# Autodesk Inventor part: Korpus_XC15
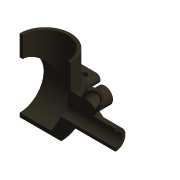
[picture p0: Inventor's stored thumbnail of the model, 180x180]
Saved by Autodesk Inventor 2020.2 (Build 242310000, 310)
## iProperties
Created: 2000-05
Part Number: Korpus_XC15
Document SubType Name: Modeling
Designer: F.Stasiak
Stock Number: Korpus_XC15
Density: 7.15 g/cm^3
Material: Żelazo, odlew
Appearance: Brąz armatni (nowy/polerowany)
Mass: 7300.3 g
Surface Area: 1792.14 cm^2
Volume: 1021.02 cm^3
Catalog Web Link: www.expertbooks.pl
Manager: www.cadconsulting.pl
Company: Fabian Stasiak CAD Consulting
Control State: 0
Master: False
Checked Out: False
Shininess: 0.0
Density: 0.0
Volumn: 0.0
Area: 0.0
PropertySet Name: Model Information
Author: F.Stasiak
Subject: Zbiór ćwiczeń. Autodesk Inventor 2020. Kurs Professional
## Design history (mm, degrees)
node "Base1"
feature "Podział1"
node "Bryła1"
node "Korpusy bryłowe"
node "Korpusy powierzchniowe"
